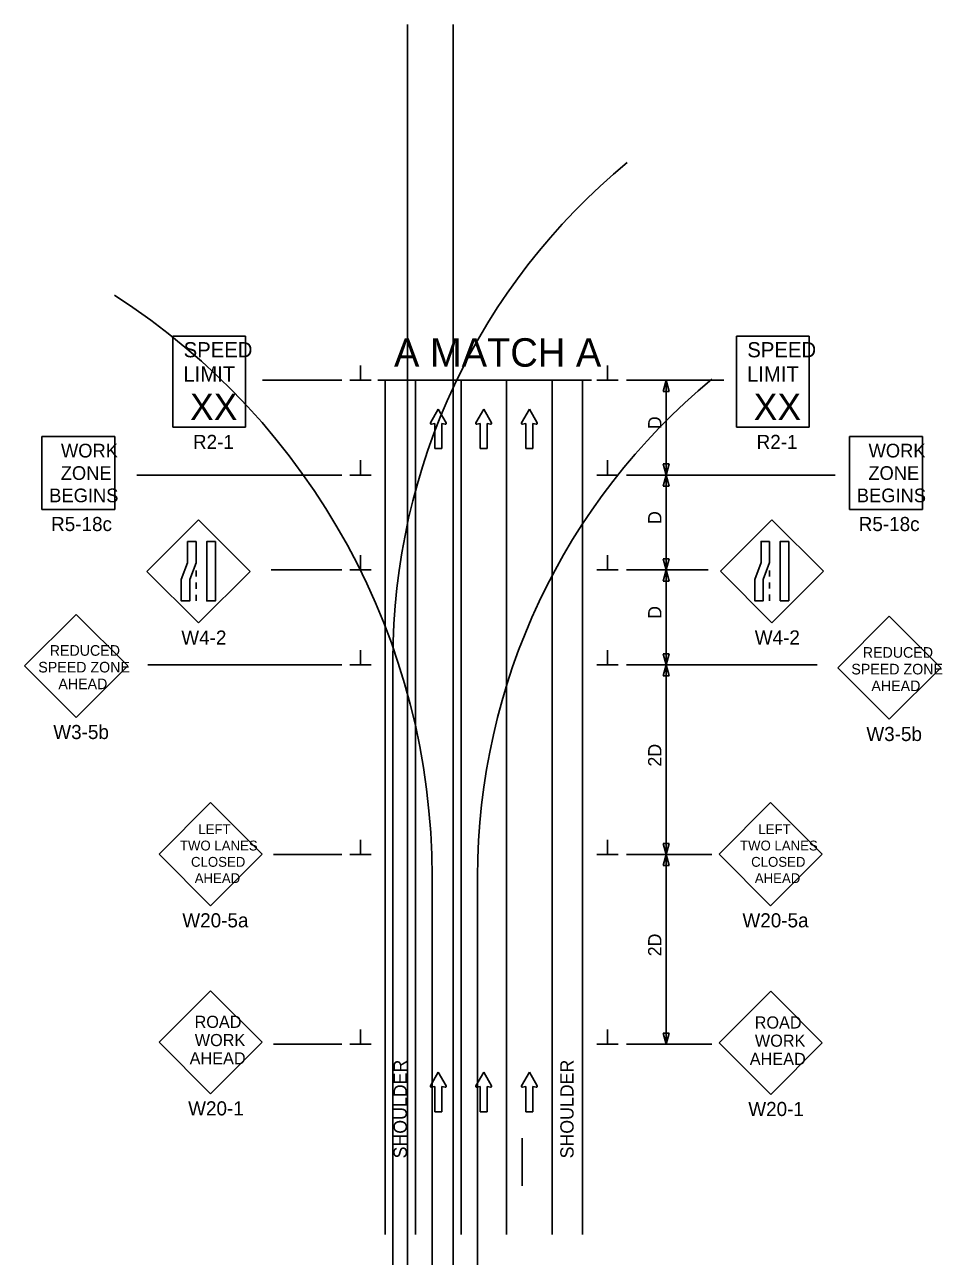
# Model space of a CAD drawing. Extents: x 16452 to 19504, y 5713 to 7079.
# Drawn here: x 17853 to 18336, y 6430 to 7079 of the extents above; entities that cross this region are included whole.
import ezdxf

# ---------------------------------------------------------------- set-up
doc = ezdxf.new("R2010")
doc.units = 0
for name, color, linetype in [('ALI_LEGAL_EX', 7, 'Continuous'), ('MT_SCRATCH_LEVEL_E', 7, 'Continuous'), ('PAVT_EDGE_EX', 7, 'Continuous'), ('TRAFFIC_SIGNS_PR', 7, 'Continuous'), ('TYPICAL_TEXT_DIMEN_PR', 7, 'Continuous')]:
    doc.layers.add(name, color=color, linetype=linetype)

msp = doc.modelspace()

# ---------------------------------------------------------------- linework, layer by layer
at = {"layer": 'ALI_LEGAL_EX'}
for p, q in [((18054.48, 7078.99), (18054.48, 6260.86)), ((18078.48, 7078.99), (18078.48, 6260.86)), ((18054.48, 6981.91), (18054.48, 6118)), ((18078.48, 6981.91), (18078.48, 6118)), ((18082.72, 6441.2), (18082.72, 6891.55)), ((18106.72, 6441.2), (18106.72, 6891.55)), ((18046.81, 6243.91), (18046.81, 6744.25)), ((18067.45, 6129.67), (18067.45, 6630.02)), ((18091.45, 6129.67), (18091.45, 6630.02))]:
    msp.add_line(p, q, dxfattribs=at)
for points in [[(18082.81, 6871.42), (18082.81, 6846.42)], [(18082.72, 6841.2), (18082.72, 6866.2)], [(18106.72, 6841.2), (18106.72, 6866.2)], [(18082.72, 6741.2), (18082.72, 6766.2)], [(18106.72, 6741.2), (18106.72, 6766.2)], [(18082.72, 6641.2), (18082.72, 6666.2)], [(18106.72, 6641.2), (18106.72, 6666.2)], [(18082.72, 6541.2), (18082.72, 6566.2)], [(18106.72, 6541.2), (18106.72, 6566.2)], [(18082.81, 6521.86), (18082.81, 6496.86)], [(18114.95, 6491.99), (18114.95, 6466.99)], [(18082.72, 6441.2), (18082.72, 6466.2)], [(18106.72, 6441.2), (18106.72, 6466.2)]]:
    msp.add_lwpolyline(points, dxfattribs=at)
for centre, radius, start, end in [((18386.81, 6744.25), 340, 129.56655, 180), ((17703.45, 6630.02), 364, 0, 57.29578), ((18431.45, 6630.02), 340, 129.56655, 180)]:
    msp.add_arc(centre, radius, start, end, dxfattribs=at)
at = {"layer": 'MT_SCRATCH_LEVEL_E'}
for p, q in [((18070.73, 6876.38), (18066.62, 6869.14)), ((18074.88, 6869.14), (18070.73, 6876.38)), ((18094.64, 6876.38), (18090.53, 6869.14)), ((18098.78, 6869.14), (18094.64, 6876.38)), ((18118.69, 6876.38), (18114.58, 6869.14)), ((18122.84, 6869.14), (18118.69, 6876.38)), ((18067.1, 6868.46), (18068.88, 6868.77)), ((18068.88, 6868.77), (18068.88, 6855.51)), ((18072.62, 6855.51), (18072.62, 6868.77)), ((18072.62, 6868.77), (18074.4, 6868.46)), ((18091.01, 6868.46), (18092.78, 6868.77)), ((18092.78, 6868.77), (18092.78, 6855.51)), ((18096.53, 6855.51), (18096.53, 6868.77)), ((18096.53, 6868.77), (18098.3, 6868.46)), ((18115.06, 6868.46), (18116.84, 6868.77)), ((18116.84, 6868.77), (18116.84, 6855.51)), ((18120.58, 6855.51), (18120.58, 6868.77)), ((18120.58, 6868.77), (18122.36, 6868.46)), ((18068.88, 6855.51), (18072.62, 6855.51)), ((18092.78, 6855.51), (18096.53, 6855.51)), ((18116.84, 6855.51), (18120.58, 6855.51)), ((18070.73, 6526.83), (18066.62, 6519.59)), ((18074.88, 6519.59), (18070.73, 6526.83)), ((18094.64, 6526.83), (18090.53, 6519.59)), ((18098.78, 6519.59), (18094.64, 6526.83)), ((18118.69, 6526.83), (18114.58, 6519.59)), ((18122.84, 6519.59), (18118.69, 6526.83)), ((18067.1, 6518.9), (18068.88, 6519.22)), ((18068.88, 6519.22), (18068.88, 6505.96)), ((18072.62, 6505.96), (18072.62, 6519.22)), ((18072.62, 6519.22), (18074.4, 6518.9)), ((18091.01, 6518.9), (18092.78, 6519.22)), ((18092.78, 6519.22), (18092.78, 6505.96)), ((18096.53, 6505.96), (18096.53, 6519.22)), ((18096.53, 6519.22), (18098.3, 6518.9)), ((18115.06, 6518.9), (18116.84, 6519.22)), ((18116.84, 6519.22), (18116.84, 6505.96)), ((18120.58, 6505.96), (18120.58, 6519.22)), ((18120.58, 6519.22), (18122.36, 6518.9)), ((18068.88, 6505.96), (18072.62, 6505.96)), ((18092.78, 6505.96), (18096.53, 6505.96)), ((18116.84, 6505.96), (18120.58, 6505.96))]:
    msp.add_line(p, q, dxfattribs=at)
for centre, start, end in [((18067.03, 6868.91), 150.42484, 279.96381), ((18074.47, 6868.91), 260.03619, 29.77312), ((18090.93, 6868.91), 150.42484, 279.96381), ((18098.37, 6868.91), 260.03619, 29.77312), ((18114.99, 6868.91), 150.42484, 279.96381), ((18122.43, 6868.91), 260.03619, 29.77312), ((18067.03, 6519.36), 150.42484, 279.96381), ((18074.47, 6519.36), 260.03619, 29.77312), ((18090.93, 6519.36), 150.42484, 279.96381), ((18098.37, 6519.36), 260.03619, 29.77312), ((18114.99, 6519.36), 150.42484, 279.96381), ((18122.43, 6519.36), 260.03619, 29.77312)]:
    msp.add_arc(centre, 0.463, start, end, dxfattribs=at)
at = {"layer": 'PAVT_EDGE_EX'}
for p, q in [((18042.72, 6891.55), (18042.72, 6441.2)), ((18058.72, 6891.55), (18058.72, 6441.2)), ((18130.72, 6891.55), (18130.72, 6441.2)), ((18146.72, 6891.55), (18146.72, 6441.2))]:
    msp.add_line(p, q, dxfattribs=at)
at = {"layer": 'TRAFFIC_SIGNS_PR'}
for p, q in [((17930.77, 6914.76), (17969.17, 6914.76)), ((17930.77, 6866.76), (17930.77, 6914.76)), ((17969.17, 6866.76), (17969.17, 6914.76)), ((18227.77, 6914.76), (18266.17, 6914.76)), ((18227.77, 6866.76), (18227.77, 6914.76)), ((18266.17, 6866.76), (18266.17, 6914.76)), ((17930.77, 6866.76), (17969.17, 6866.76)), ((18227.77, 6866.76), (18266.17, 6866.76)), ((17861.89, 6823.48), (17861.89, 6861.88)), ((17861.89, 6861.88), (17900.29, 6861.88)), ((17900.29, 6823.48), (17900.29, 6861.88)), ((18287.43, 6823.48), (18287.43, 6861.88)), ((18287.43, 6861.88), (18325.83, 6861.88)), ((18325.83, 6823.48), (18325.83, 6861.88)), ((17861.89, 6823.48), (17900.29, 6823.48)), ((17944.35, 6817.93), (17917.2, 6790.77)), ((17971.5, 6790.77), (17944.35, 6817.93)), ((18246.51, 6818), (18219.36, 6790.85)), ((18273.67, 6790.85), (18246.51, 6818)), ((18287.43, 6823.48), (18325.83, 6823.48)), ((18245.27, 6791.34), (18245.27, 6788.14)), ((17917.2, 6790.77), (17944.35, 6763.62)), ((17943.1, 6791.27), (17943.1, 6788.07)), ((17943.1, 6784.87), (17943.1, 6781.67)), ((17944.35, 6763.62), (17971.5, 6790.77)), ((18219.36, 6790.85), (18246.51, 6763.69)), ((18245.27, 6784.94), (18245.27, 6781.74)), ((18246.51, 6763.69), (18273.67, 6790.85)), ((17943.1, 6778.47), (17943.1, 6775.27)), ((18245.27, 6778.54), (18245.27, 6775.34)), ((17879.91, 6768.15), (17852.76, 6741)), ((17907.06, 6741), (17879.91, 6768.15)), ((18308.32, 6767.11), (18281.16, 6739.96)), ((18335.47, 6739.96), (18308.32, 6767.11)), ((17852.76, 6741), (17879.91, 6713.85)), ((17879.91, 6713.85), (17907.06, 6741)), ((18281.16, 6739.96), (18308.32, 6712.81)), ((18308.32, 6712.81), (18335.47, 6739.96)), ((17950.71, 6668.9), (17923.56, 6641.75)), ((17977.86, 6641.75), (17950.71, 6668.9)), ((18245.84, 6668.9), (18218.69, 6641.75)), ((18273, 6641.75), (18245.84, 6668.9)), ((17923.56, 6641.75), (17950.71, 6614.59)), ((17950.71, 6614.59), (17977.86, 6641.75)), ((18218.69, 6641.75), (18245.84, 6614.59)), ((18245.84, 6614.59), (18273, 6641.75)), ((17950.74, 6569.77), (17923.59, 6542.62)), ((17977.9, 6542.62), (17950.74, 6569.77)), ((18245.88, 6569.45), (18218.73, 6542.3)), ((18273.03, 6542.3), (18245.88, 6569.45)), ((17923.59, 6542.62), (17950.74, 6515.47)), ((17950.74, 6515.47), (17977.9, 6542.62)), ((18218.73, 6542.3), (18245.88, 6515.14)), ((18245.88, 6515.14), (18273.03, 6542.3))]:
    msp.add_line(p, q, dxfattribs=at)
for points in [[(17943.1, 6806.51), (17943.1, 6795.33), (17939.76, 6786.45), (17939.76, 6775.27), (17935.26, 6775.27), (17935.26, 6786.45), (17938.61, 6795.33), (17938.61, 6806.51)], [(17953.24, 6806.51), (17953.24, 6775.27), (17948.75, 6775.27), (17948.75, 6806.51)], [(18245.27, 6806.58), (18245.27, 6795.4), (18241.92, 6786.52), (18241.92, 6775.34), (18237.43, 6775.34), (18237.43, 6786.52), (18240.77, 6795.4), (18240.77, 6806.58)], [(18255.4, 6806.58), (18255.4, 6775.34), (18250.91, 6775.34), (18250.91, 6806.58)]]:
    msp.add_lwpolyline(points, close=True, dxfattribs=at)
at = {"layer": 'TYPICAL_TEXT_DIMEN_PR'}
for p, q in [((18029.69, 6891.55), (18029.69, 6899.34)), ((18159.94, 6891.55), (18159.94, 6899.34)), ((17978.12, 6891.55), (18019.81, 6891.55)), ((18024.06, 6891.55), (18035.31, 6891.55)), ((18038.79, 6891.55), (18151.44, 6891.55)), ((18165.56, 6891.55), (18154.31, 6891.55)), ((18169.81, 6891.55), (18221.23, 6891.55)), ((18189.24, 6885.69), (18190.81, 6891.55)), ((18190.81, 6891.55), (18190.81, 6841.55)), ((18190.81, 6891.55), (18192.39, 6885.69)), ((18190.81, 6885.69), (18189.24, 6885.69)), ((18192.39, 6885.69), (18190.81, 6885.69)), ((18029.69, 6841.55), (18029.69, 6849.34)), ((18159.94, 6841.55), (18159.94, 6849.34)), ((18190.81, 6841.55), (18189.24, 6847.41)), ((18189.24, 6847.41), (18190.81, 6847.41)), ((18190.81, 6847.41), (18192.39, 6847.41)), ((18192.39, 6847.41), (18190.81, 6841.55)), ((18019.81, 6841.55), (17911.9, 6841.55)), ((18024.06, 6841.55), (18035.31, 6841.55)), ((18165.56, 6841.55), (18154.31, 6841.55)), ((18169.81, 6841.55), (18279.77, 6841.55)), ((18189.24, 6835.69), (18190.81, 6841.55)), ((18190.81, 6841.55), (18192.39, 6835.69)), ((18190.81, 6841.55), (18190.81, 6791.55)), ((18190.81, 6835.69), (18189.24, 6835.69)), ((18192.39, 6835.69), (18190.81, 6835.69)), ((18029.69, 6791.55), (18029.69, 6799.34)), ((18159.94, 6791.55), (18159.94, 6799.34)), ((18019.81, 6791.55), (17982.61, 6791.55)), ((18024.06, 6791.55), (18035.31, 6791.55)), ((18165.56, 6791.55), (18154.31, 6791.55)), ((18169.81, 6791.55), (18212.93, 6791.55)), ((18190.81, 6791.55), (18189.24, 6797.41)), ((18189.24, 6797.41), (18190.81, 6797.41)), ((18189.24, 6785.69), (18190.81, 6791.55)), ((18190.81, 6797.41), (18192.39, 6797.41)), ((18192.39, 6797.41), (18190.81, 6791.55)), ((18190.81, 6791.55), (18190.81, 6741.55)), ((18190.81, 6791.55), (18192.39, 6785.69)), ((18190.81, 6785.69), (18189.24, 6785.69)), ((18192.39, 6785.69), (18190.81, 6785.69)), ((18029.69, 6741.55), (18029.69, 6749.34)), ((18159.94, 6741.55), (18159.94, 6749.34)), ((18190.81, 6741.55), (18189.24, 6747.41)), ((18189.24, 6747.41), (18190.81, 6747.41)), ((18190.81, 6747.41), (18192.39, 6747.41)), ((18192.39, 6747.41), (18190.81, 6741.55)), ((17917.58, 6741.55), (18019.81, 6741.55)), ((18024.06, 6741.55), (18035.31, 6741.55)), ((18165.56, 6741.55), (18154.31, 6741.55)), ((18169.81, 6741.55), (18270.41, 6741.55)), ((18189.24, 6735.69), (18190.81, 6741.55)), ((18190.81, 6741.55), (18190.81, 6641.55)), ((18190.81, 6741.55), (18192.39, 6735.69)), ((18190.81, 6735.69), (18189.24, 6735.69)), ((18192.39, 6735.69), (18190.81, 6735.69)), ((18029.69, 6641.55), (18029.69, 6649.34)), ((18159.94, 6641.55), (18159.94, 6649.34)), ((18190.81, 6641.55), (18189.24, 6647.41)), ((18189.24, 6647.41), (18190.81, 6647.41)), ((18190.81, 6647.41), (18192.39, 6647.41)), ((18192.39, 6647.41), (18190.81, 6641.55)), ((18019.81, 6641.55), (17983.81, 6641.55)), ((18024.06, 6641.55), (18035.31, 6641.55)), ((18165.56, 6641.55), (18154.31, 6641.55)), ((18169.81, 6641.55), (18214.92, 6641.55)), ((18189.24, 6635.69), (18190.81, 6641.55)), ((18190.81, 6635.69), (18189.24, 6635.69)), ((18190.81, 6641.55), (18190.81, 6541.55)), ((18190.81, 6641.55), (18192.39, 6635.69)), ((18192.39, 6635.69), (18190.81, 6635.69)), ((18029.69, 6541.55), (18029.69, 6549.34)), ((18159.94, 6541.55), (18159.94, 6549.34)), ((18190.81, 6541.55), (18189.24, 6547.41)), ((18189.24, 6547.41), (18190.81, 6547.41)), ((18190.81, 6547.41), (18192.39, 6547.41)), ((18192.39, 6547.41), (18190.81, 6541.55)), ((18019.81, 6541.55), (17983.81, 6541.55)), ((18024.06, 6541.55), (18035.31, 6541.55)), ((18165.56, 6541.55), (18154.31, 6541.55)), ((18169.81, 6541.55), (18214.92, 6541.55))]:
    msp.add_line(p, q, dxfattribs=at)

# ---------------------------------------------------------------- texts
at = {"layer": 'TRAFFIC_SIGNS_PR'}
for s, height, p in [('SPEED', 8, (17936.53, 6903.63)), ('SPEED', 8, (18233.53, 6903.63)), ('LIMIT', 8, (17936.37, 6890.83)), ('LIMIT', 8, (18233.37, 6890.83)), ('XX', 14.031, (17939.88, 6870.52)), ('XX', 14.031, (18236.88, 6870.52)), ('R2-1', 7.44, (17941.44, 6855.32)), ('R2-1', 7.44, (18238.44, 6855.32)), ('WORK', 7.217, (17871.89, 6850.84)), ('WORK', 7.217, (18297.43, 6850.84)), ('ZONE', 7.217, (17871.77, 6839.03)), ('ZONE', 7.217, (18297.31, 6839.03)), ('BEGINS', 7.217, (17865.7, 6827.23)), ('BEGINS', 7.217, (18291.24, 6827.23)), ('R5-18c', 7.44, (17866.7, 6812.04)), ('R5-18c', 7.44, (18292.24, 6812.04)), ('W4-2', 7.44, (17935.31, 6752.18)), ('W4-2', 7.44, (18237.47, 6752.25)), ('REDUCED', 5.6, (17865.97, 6746.31)), ('REDUCED', 5.6, (18294.37, 6745.27)), ('SPEED ZONE', 5.6, (17859.96, 6737.51)), ('SPEED ZONE', 5.6, (18288.37, 6736.47)), ('AHEAD', 5.6, (17870.52, 6728.71)), ('AHEAD', 5.6, (18298.93, 6727.67)), ('W3-5b', 7.44, (17867.86, 6702.41)), ('W3-5b', 7.44, (18296.27, 6701.37)), ('LEFT', 5.2, (17944.25, 6652.28)), ('LEFT', 5.2, (18239.38, 6652.28)), ('TWO LANES', 5.2, (17934.57, 6643.68)), ('TWO LANES', 5.2, (18229.7, 6643.68)), ('CLOSED', 5.2, (17940.42, 6635.08)), ('CLOSED', 5.2, (18235.56, 6635.08)), ('AHEAD', 5.2, (17942.37, 6626.48)), ('AHEAD', 5.2, (18237.5, 6626.48)), ('W20-5a', 7.44, (17935.85, 6603.15)), ('W20-5a', 7.44, (18230.98, 6603.15)), ('ROAD', 6.4, (17942.29, 6550.16)), ('ROAD', 6.4, (18237.42, 6549.83)), ('WORK', 6.4, (17942.39, 6540.56)), ('WORK', 6.4, (18237.53, 6540.23)), ('AHEAD', 6.4, (17939.7, 6530.96)), ('AHEAD', 6.4, (18234.84, 6530.63)), ('W20-1', 7.44, (17938.91, 6504.03)), ('W20-1', 7.44, (18234.05, 6503.7))]:
    msp.add_text(s, height=height, dxfattribs=at).set_placement(p)
at = {"layer": 'TYPICAL_TEXT_DIMEN_PR'}
msp.add_text('A MATCH A', height=15, dxfattribs=at).set_placement((18047.38, 6898.69))
for s, p in [('D', (18188.26, 6865.77)), ('D', (18188.26, 6815.77)), ('D', (18188.26, 6765.77)), ('2D', (18188.26, 6687.91)), ('2D', (18188.26, 6587.91)), ('SHOULDER', (18054.15, 6481.37)), ('SHOULDER', (18142.01, 6481.37))]:
    msp.add_text(s, height=7, rotation=90, dxfattribs=at).set_placement(p)

doc.saveas('drawing.dxf')
